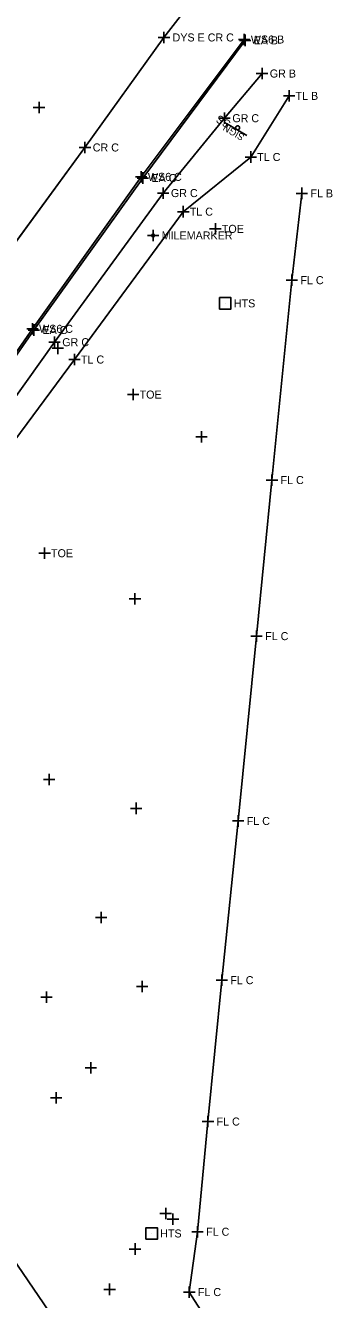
# Model space of a CAD drawing. Extents: x 1324236 to 1326110, y 459090 to 460782.
# Drawn here: x 1325457.8 to 1325511.5, y 460303.9 to 460526.7 of the extents above; entities that cross this region are included whole.
import ezdxf

# ---------------------------------------------------------------- set-up
doc = ezdxf.new("R2010")
doc.units = 0
for name, color, linetype in [('BD_X_Canopy', 7, 'Continuous'), ('DR_X_Ditch', 7, 'Continuous'), ('DR_X_Drive_Pipe', 7, 'Continuous'), ('DR_X_Storm_Sewer', 7, 'Continuous'), ('DT_X_Contour_Major', 7, 'Continuous'), ('DT_X_Contour_Minor', 7, 'Continuous'), ('DT_X_Island', 7, 'Continuous'), ('DV_X_Property_Line', 7, 'Continuous'), ('LT_X_Poles', 7, 'Continuous'), ('PM_X_CL_Double_Solid', 7, 'Continuous'), ('PM_X_Edge_Line', 7, 'Continuous'), ('PM_X_Parking_Lot_Stall', 7, 'Continuous'), ('PV_X_Shoulder', 7, 'Continuous'), ('RD_X_Concrete_Barrier', 7, 'Continuous'), ('RD_X_GR_Lt', 7, 'Continuous'), ('RW_X_CL', 7, 'Continuous'), ('RW_X_Esmt_SH', 7, 'Continuous')]:
    doc.layers.add(name, color=color, linetype=linetype)

msp = doc.modelspace()

# ---------------------------------------------------------------- linework, layer by layer
at = {"layer": 'BD_X_Canopy'}
msp.add_lwpolyline([(1325487.31, 460531.49), (1325482.01, 460524.62), (1325468.2, 460505.38), (1325449.72, 460480.14), (1325435.41, 460460.81), (1325430.06, 460453.47), (1325411.08, 460426.97), (1325392.29, 460401.31), (1325374.47, 460377.45), (1325359.08, 460355.34), (1325347.31, 460339.76), (1325334.63, 460323.86), (1325318.91, 460302.58), (1325303.42, 460281.57), (1325299.27, 460276.07), (1325289.28, 460262.48), (1325282.05, 460252.54), (1325264.96, 460229.27), (1325246.47, 460204.3), (1325228.59, 460180.03), (1325210.75, 460156.01)], dxfattribs=at)
at = {"layer": 'DR_X_Ditch'}
msp.add_lwpolyline([(1325496.02, 460524.26), (1325478.04, 460500.24), (1325459.02, 460473.66), (1325440.01, 460446.4)], dxfattribs=at)
at = {"layer": 'DR_X_Drive_Pipe'}
msp.add_line((1325445.1, 460326.41), (1325463.76, 460299.09), dxfattribs=at)
at = {"layer": 'DR_X_Storm_Sewer'}
msp.add_line((1325487.31, 460531.49), (1325482.01, 460524.62), dxfattribs=at)
at = {"layer": 'DT_X_Contour_Major'}
for p, q in [((1325492.72, 460478.11), (1325492.72, 460478.11)), ((1325479.85, 460315.44), (1325479.85, 460315.44))]:
    msp.add_line(p, q, dxfattribs=at)
for points in [[(1325491.72, 460477.11), (1325491.72, 460479.11), (1325493.72, 460479.11), (1325493.72, 460477.11), (1325491.72, 460477.11)], [(1325478.85, 460314.44), (1325478.85, 460316.44), (1325480.85, 460316.44), (1325480.85, 460314.44), (1325478.85, 460314.44)]]:
    msp.add_lwpolyline(points, dxfattribs=at)
at = {"layer": 'DT_X_Contour_Minor'}
msp.add_line((1325496.48, 460507.47), (1325492.92, 460509.57), dxfattribs=at)
msp.add_circle((1325494.88, 460508.82), 0.344, dxfattribs=at)
at = {"layer": 'DT_X_Island'}
for p, q in [((1325487.31, 460531.49), (1325482.01, 460524.62)), ((1325482.01, 460524.62), (1325468.2, 460505.38)), ((1325468.2, 460505.38), (1325449.72, 460480.14))]:
    msp.add_line(p, q, dxfattribs=at)
at = {"layer": 'DV_X_Property_Line'}
for p, q in [((1325496.18, 460523.11), (1325496.18, 460525.11)), ((1325495.18, 460524.11), (1325497.18, 460524.11)), ((1325492.59, 460509.5), (1325492.59, 460511.5)), ((1325491.59, 460510.5), (1325493.59, 460510.5)), ((1325478.32, 460499.03), (1325478.32, 460501.03)), ((1325477.32, 460500.03), (1325479.32, 460500.03)), ((1325459.28, 460472.45), (1325459.28, 460474.45)), ((1325458.28, 460473.45), (1325460.28, 460473.45))]:
    msp.add_line(p, q, dxfattribs=at)
at = {"layer": 'LT_X_Poles'}
msp.add_line((1325487.31, 460531.49), (1325482.01, 460524.62), dxfattribs=at)
msp.add_lwpolyline([(1325496.02, 460524.26), (1325478.04, 460500.24), (1325459.02, 460473.66), (1325440.01, 460446.4)], dxfattribs=at)
at = {"layer": 'PM_X_CL_Double_Solid'}
for p, q in [((1325506.11, 460497.35), (1325504.35, 460482.17)), ((1325504.35, 460482.17), (1325500.88, 460447.21)), ((1325500.88, 460447.21), (1325498.19, 460419.91)), ((1325498.19, 460419.91), (1325494.97, 460387.58)), ((1325494.97, 460387.58), (1325492.1, 460359.74)), ((1325492.1, 460359.74), (1325489.7, 460335.01)), ((1325489.7, 460335.01), (1325487.87, 460315.74)), ((1325487.87, 460315.74), (1325486.43, 460305.19)), ((1325486.43, 460305.19), (1325500.93, 460282.45))]:
    msp.add_line(p, q, dxfattribs=at)
at = {"layer": 'PM_X_Edge_Line'}
for p, q in [((1325496.02, 460524.26), (1325478.04, 460500.24)), ((1325478.04, 460500.24), (1325459.02, 460473.66)), ((1325459.02, 460473.66), (1325440.01, 460446.4))]:
    msp.add_line(p, q, dxfattribs=at)
at = {"layer": 'PM_X_Parking_Lot_Stall'}
for p, q in [((1325499.14, 460518.31), (1325492.59, 460510.5)), ((1325492.59, 460510.5), (1325481.86, 460497.4)), ((1325481.86, 460497.4), (1325462.87, 460471.32)), ((1325462.87, 460471.32), (1325443.39, 460444.01))]:
    msp.add_line(p, q, dxfattribs=at)
at = {"layer": 'PV_X_Shoulder'}
msp.add_lwpolyline([(1325496.18, 460524.11), (1325478.32, 460500.03), (1325459.28, 460473.45), (1325440.31, 460446.28)], dxfattribs=at)
at = {"layer": 'RD_X_Concrete_Barrier'}
msp.add_circle((1325480.11, 460489.99), 0.25, dxfattribs=at)
at = {"layer": 'RD_X_GR_Lt'}
for p, q in [((1325497.18, 460503.71), (1325503.87, 460514.4)), ((1325485.39, 460494.15), (1325497.18, 460503.71)), ((1325466.37, 460468.29), (1325485.39, 460494.15)), ((1325446.9, 460442.01), (1325466.37, 460468.29))]:
    msp.add_line(p, q, dxfattribs=at)
at = {"layer": 'RW_X_CL'}
for p, q in [((1325482.01, 460523.62), (1325482.01, 460525.62)), ((1325496.02, 460523.26), (1325496.02, 460525.26)), ((1325481.01, 460524.62), (1325483.01, 460524.62)), ((1325495.02, 460524.26), (1325497.02, 460524.26)), ((1325459.17, 460512.37), (1325461.17, 460512.37)), ((1325460.17, 460511.37), (1325460.17, 460513.37)), ((1325467.2, 460505.38), (1325469.2, 460505.38)), ((1325468.2, 460504.38), (1325468.2, 460506.38)), ((1325477.04, 460500.24), (1325479.04, 460500.24)), ((1325478.04, 460499.24), (1325478.04, 460501.24)), ((1325479.11, 460489.99), (1325481.11, 460489.99)), ((1325480.11, 460488.99), (1325480.11, 460490.99)), ((1325458.02, 460473.66), (1325460.02, 460473.66)), ((1325459.02, 460472.66), (1325459.02, 460474.66)), ((1325463.45, 460469.25), (1325463.45, 460471.25)), ((1325462.45, 460470.25), (1325464.45, 460470.25)), ((1325488.55, 460453.75), (1325488.55, 460455.75)), ((1325487.55, 460454.75), (1325489.55, 460454.75)), ((1325476.94, 460425.45), (1325476.94, 460427.45)), ((1325475.94, 460426.45), (1325477.94, 460426.45)), ((1325461.96, 460393.83), (1325461.96, 460395.83)), ((1325460.96, 460394.83), (1325462.96, 460394.83)), ((1325476.16, 460389.79), (1325478.16, 460389.79)), ((1325477.16, 460388.79), (1325477.16, 460390.79)), ((1325471.03, 460369.71), (1325471.03, 460371.71)), ((1325470.03, 460370.71), (1325472.03, 460370.71)), ((1325461.48, 460355.78), (1325461.48, 460357.78)), ((1325477.2, 460358.64), (1325479.2, 460358.64)), ((1325478.2, 460357.64), (1325478.2, 460359.64)), ((1325460.48, 460356.78), (1325462.48, 460356.78)), ((1325468.23, 460344.41), (1325470.23, 460344.41)), ((1325469.23, 460343.41), (1325469.23, 460345.41)), ((1325463.15, 460338.18), (1325463.15, 460340.18)), ((1325462.15, 460339.18), (1325464.15, 460339.18)), ((1325482.31, 460317.94), (1325482.31, 460319.94)), ((1325481.31, 460318.94), (1325483.31, 460318.94)), ((1325482.58, 460317.94), (1325484.58, 460317.94)), ((1325483.58, 460316.94), (1325483.58, 460318.94)), ((1325476.95, 460311.72), (1325476.95, 460313.72)), ((1325475.95, 460312.72), (1325477.95, 460312.72)), ((1325472.51, 460304.66), (1325472.51, 460306.66)), ((1325471.51, 460305.66), (1325473.51, 460305.66))]:
    msp.add_line(p, q, dxfattribs=at)
at = {"layer": 'RW_X_Esmt_SH'}
for p, q in [((1325498.14, 460518.31), (1325500.14, 460518.31)), ((1325499.14, 460517.31), (1325499.14, 460519.31)), ((1325502.87, 460514.4), (1325504.87, 460514.4)), ((1325503.87, 460513.4), (1325503.87, 460515.4)), ((1325497.18, 460502.71), (1325497.18, 460504.71)), ((1325496.18, 460503.71), (1325498.18, 460503.71)), ((1325481.86, 460496.4), (1325481.86, 460498.4)), ((1325506.11, 460496.35), (1325506.11, 460498.35)), ((1325480.86, 460497.4), (1325482.86, 460497.4)), ((1325505.11, 460497.35), (1325507.11, 460497.35)), ((1325484.39, 460494.15), (1325486.39, 460494.15)), ((1325485.39, 460493.15), (1325485.39, 460495.15)), ((1325490.99, 460490.14), (1325490.99, 460492.14)), ((1325489.99, 460491.14), (1325491.99, 460491.14)), ((1325504.35, 460481.17), (1325504.35, 460483.17)), ((1325503.35, 460482.17), (1325505.35, 460482.17)), ((1325461.87, 460471.32), (1325463.87, 460471.32)), ((1325462.87, 460470.32), (1325462.87, 460472.32)), ((1325466.37, 460467.29), (1325466.37, 460469.29)), ((1325465.37, 460468.29), (1325467.37, 460468.29)), ((1325476.63, 460461.16), (1325476.63, 460463.16)), ((1325475.63, 460462.16), (1325477.63, 460462.16)), ((1325499.88, 460447.21), (1325501.88, 460447.21)), ((1325500.88, 460446.21), (1325500.88, 460448.21)), ((1325460.15, 460434.41), (1325462.15, 460434.41)), ((1325461.15, 460433.41), (1325461.15, 460435.41)), ((1325498.19, 460418.91), (1325498.19, 460420.91)), ((1325497.19, 460419.91), (1325499.19, 460419.91)), ((1325493.97, 460387.58), (1325495.97, 460387.58)), ((1325494.97, 460386.58), (1325494.97, 460388.58)), ((1325492.1, 460358.74), (1325492.1, 460360.74)), ((1325491.1, 460359.74), (1325493.1, 460359.74)), ((1325489.7, 460334.01), (1325489.7, 460336.01)), ((1325488.7, 460335.01), (1325490.7, 460335.01)), ((1325486.87, 460315.74), (1325488.87, 460315.74)), ((1325487.87, 460314.74), (1325487.87, 460316.74)), ((1325485.43, 460305.19), (1325487.43, 460305.19)), ((1325486.43, 460304.19), (1325486.43, 460306.19))]:
    msp.add_line(p, q, dxfattribs=at)

# ---------------------------------------------------------------- texts
at = {"layer": 'DT_X_Contour_Major'}
for p in [(1325494.22, 460477.41), (1325481.35, 460314.74)]:
    msp.add_text('HTS', height=1.4, dxfattribs=at).set_placement(p)
at = {"layer": 'DT_X_Contour_Minor'}
for s, height, p in [('SS', 1.4, (1325493.81, 460509.86)), ('SIGN', 1.205, (1325496.19, 460507.52))]:
    msp.add_text(s, height=height, rotation=149.5205, dxfattribs=at).set_placement(p)
at = {"layer": 'DV_X_Property_Line'}
for s, p in [('EA B', (1325497.68, 460523.41)), ('GR C', (1325493.95, 460509.8)), ('EA C', (1325479.82, 460499.33)), ('EA C', (1325460.78, 460472.75))]:
    msp.add_text(s, height=1.4, dxfattribs=at).set_placement(p)
at = {"layer": 'RW_X_CL'}
for s, p in [('DYS E CR C', (1325483.51, 460523.92)), ('WS6 B', (1325497.19, 460523.56)), ('CR C', (1325469.56, 460504.68)), ('WS6 C', (1325479.2, 460499.54)), ('MILEMARKER', (1325481.61, 460489.29)), ('WS6 C', (1325460.18, 460472.96))]:
    msp.add_text(s, height=1.4, dxfattribs=at).set_placement(p)
at = {"layer": 'RW_X_Esmt_SH'}
for s, p in [('GR B', (1325500.5, 460517.61)), ('TL B', (1325505, 460513.7)), ('TL C', (1325498.3, 460503.01)), ('GR C', (1325483.22, 460496.7)), ('FL B', (1325507.61, 460496.65)), ('TL C', (1325486.51, 460493.45)), ('TOE', (1325492.12, 460490.44)), ('FL C', (1325505.85, 460481.47)), ('GR C', (1325464.23, 460470.62)), ('TL C', (1325467.5, 460467.59)), ('TOE', (1325477.75, 460461.46)), ('FL C', (1325502.38, 460446.51)), ('TOE', (1325462.27, 460433.71)), ('FL C', (1325499.69, 460419.21)), ('FL C', (1325496.47, 460386.88)), ('FL C', (1325493.6, 460359.04)), ('FL C', (1325491.2, 460334.31)), ('FL C', (1325489.37, 460315.04)), ('FL C', (1325487.93, 460304.49))]:
    msp.add_text(s, height=1.4, dxfattribs=at).set_placement(p)

doc.saveas('drawing.dxf')
